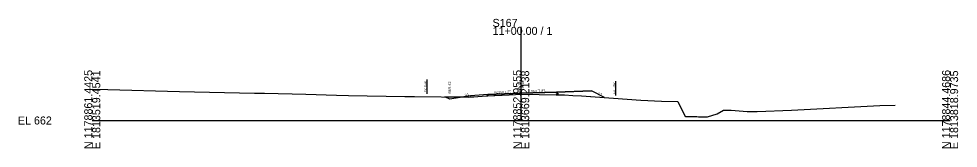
# Model space of a CAD drawing. Extents: x -26 to 6803, y -10 to 1023.
# Drawn here: x -25.7 to 302.8, y 490.3 to 535.6 of the extents above; entities that cross this region are included whole.
import ezdxf

# ---------------------------------------------------------------- set-up
doc = ezdxf.new("R2010")
doc.units = 0
for name, color, linetype in [('Default', 7, 'Continuous'), ('RD_EX_RW', 7, 'Continuous'), ('RD_GPK_XS_Cell', 7, 'Continuous'), ('RD_XS_Base', 7, 'Continuous'), ('RD_XS_EarthShd', 7, 'Continuous'), ('RD_XS_ExGround', 7, 'Continuous'), ('RD_XS_Misc_Line', 7, 'Continuous'), ('RD_XS_Pave', 7, 'Continuous'), ('RD_XS_TieSlope', 7, 'Continuous'), ('RD_XS_TX_Elev_EX', 7, 'Continuous'), ('RD_XS_TX_Elev_PR', 7, 'Continuous'), ('RD_XS_TX_Slope', 7, 'Continuous')]:
    doc.layers.add(name, color=color, linetype=linetype)

msp = doc.modelspace()

# ---------------------------------------------------------------- linework, layer by layer
at = {"layer": 'Default'}
for p, q in [((138.33, 509.14), (150, 509.54)), ((150, 509.54), (162.36, 509.94))]:
    msp.add_line(p, q, dxfattribs=at)
at = {"layer": 'RD_EX_RW'}
for p, q in [((117, 514.32), (117, 509.32)), ((183, 513.74), (183, 508.74))]:
    msp.add_line(p, q, dxfattribs=at)
at = {"layer": 'RD_GPK_XS_Cell'}
for p, q in [((150, 500), (150, 532.74)), ((0, 500), (150, 500)), ((150, 500), (300, 500))]:
    msp.add_line(p, q, dxfattribs=at)
at = {"layer": 'RD_XS_Base'}
for p, q in [((162.24, 508.94), (162.24, 509)), ((162.36, 508.94), (162.24, 508.94))]:
    msp.add_line(p, q, dxfattribs=at)
at = {"layer": 'RD_XS_EarthShd'}
for p, q in [((162.36, 509.94), (174.58, 510.34)), ((138.33, 509.14), (132.33, 508.64))]:
    msp.add_line(p, q, dxfattribs=at)
at = {"layer": 'RD_XS_ExGround'}
for p, q in [((0, 510.91), (5.4, 510.88)), ((5.4, 510.88), (30.5, 510.2)), ((30.5, 510.2), (56.74, 509.54)), ((56.74, 509.54), (60.18, 509.57)), ((60.18, 509.57), (74.68, 509.24)), ((74.68, 509.24), (85.43, 508.81)), ((85.43, 508.81), (89.62, 508.74)), ((89.62, 508.74), (109.26, 508.39)), ((109.26, 508.39), (111.56, 508.35)), ((111.56, 508.35), (112.73, 508.34)), ((112.73, 508.34), (131.5, 508.22)), ((131.5, 508.22), (132.22, 508.25)), ((132.22, 508.25), (133.4, 508.31)), ((133.4, 508.31), (137.76, 508.6)), ((137.76, 508.6), (145.82, 508.96)), ((145.82, 508.96), (150.23, 509.17)), ((150.23, 509.17), (162.3, 509)), ((162.3, 509), (163.67, 508.98)), ((163.67, 508.98), (165.12, 508.97)), ((165.12, 508.97), (168.12, 508.78)), ((168.12, 508.78), (171.06, 508.67)), ((171.06, 508.67), (191.82, 507.06)), ((191.82, 507.06), (199.12, 506.76)), ((199.12, 506.76), (204.8, 506.68)), ((204.8, 506.68), (207.29, 501.67)), ((218.51, 502.39), (220.74, 503.64)), ((220.74, 503.64), (223.41, 503.58)), ((223.41, 503.58), (228.98, 503.19)), ((228.98, 503.19), (232.48, 503.14)), ((232.48, 503.14), (244.57, 503.63)), ((244.57, 503.63), (275.48, 505.23)), ((275.48, 505.23), (280.76, 505.31)), ((207.29, 501.67), (207.6, 501.39)), ((207.6, 501.39), (210.92, 501.35)), ((210.92, 501.35), (211.4, 501.41)), ((211.4, 501.41), (212.02, 501.29)), ((212.02, 501.29), (215.11, 501.25)), ((215.11, 501.25), (218.51, 502.39))]:
    msp.add_line(p, q, dxfattribs=at)
at = {"layer": 'RD_XS_Misc_Line'}
for points in [[(162.24, 509), (162.3, 509), (162.86, 508.99), (162.86, 509.6), (162.36, 509.61), (162.36, 509.94), (150, 509.54), (138.33, 509.14), (138.33, 508.62), (145.82, 508.96), (150.23, 509.17)], [(162.24, 509), (162.3, 509), (162.86, 508.99), (162.86, 509.6), (162.36, 509.61), (162.36, 509.94), (150, 509.54), (138.33, 509.14), (138.33, 508.62), (145.82, 508.96), (150.23, 509.17)], [(162.24, 509), (162.3, 509), (162.86, 508.99), (162.86, 509.6), (162.36, 509.61), (162.36, 509.94), (150, 509.54), (138.33, 509.14), (138.33, 508.62), (145.82, 508.96), (150.23, 509.17)], [(162.36, 509.61), (162.36, 509.94), (150, 509.54), (138.33, 509.14), (138.33, 508.62), (145.82, 508.96), (150.23, 509.17), (162.24, 509), (162.3, 509), (162.86, 508.99), (162.86, 509.6)], [(162.36, 509.61), (162.36, 509.94), (150, 509.54), (138.33, 509.14), (138.33, 508.62), (145.82, 508.96), (150.23, 509.17), (162.24, 509), (162.3, 509), (162.86, 508.99), (162.86, 509.6)], [(162.86, 508.99), (163.67, 508.98), (165.12, 508.97), (168.12, 508.78), (171.06, 508.67), (179.18, 508.04), (174.58, 510.34), (162.36, 509.94), (162.36, 509.61), (162.86, 509.6)], [(162.86, 508.99), (163.67, 508.98), (165.12, 508.97), (168.12, 508.78), (171.06, 508.67), (179.18, 508.04), (174.58, 510.34), (162.36, 509.94), (162.36, 509.61), (162.86, 509.6)], [(162.86, 508.99), (163.67, 508.98), (165.12, 508.97), (168.12, 508.78), (171.06, 508.67), (179.18, 508.04), (174.58, 510.34), (162.36, 509.94), (162.36, 509.61), (162.86, 509.6)], [(179.18, 508.04), (174.58, 510.34), (162.36, 509.94), (162.36, 509.61), (162.86, 509.6), (162.86, 508.99), (163.67, 508.98), (165.12, 508.97), (168.12, 508.78), (171.06, 508.67)], [(179.18, 508.04), (174.58, 510.34), (162.36, 509.94), (162.36, 509.61), (162.86, 509.6), (162.86, 508.99), (163.67, 508.98), (165.12, 508.97), (168.12, 508.78), (171.06, 508.67)], [(129.89, 508.23), (125, 507.42), (123.29, 508.28)], [(129.89, 508.23), (131.5, 508.22), (132.22, 508.25), (133.4, 508.31), (137.76, 508.6), (138.33, 508.62), (138.33, 509.14), (132.33, 508.64)], [(129.89, 508.23), (131.5, 508.22), (132.22, 508.25), (133.4, 508.31), (137.76, 508.6), (138.33, 508.62), (138.33, 509.14), (132.33, 508.64)], [(129.89, 508.23), (131.5, 508.22), (132.22, 508.25), (133.4, 508.31), (137.76, 508.6), (138.33, 508.62), (138.33, 509.14), (132.33, 508.64)], [(132.33, 508.64), (129.89, 508.23), (131.5, 508.22), (132.22, 508.25), (133.4, 508.31), (137.76, 508.6), (138.33, 508.62), (138.33, 509.14)], [(132.33, 508.64), (129.89, 508.23), (131.5, 508.22), (132.22, 508.25), (133.4, 508.31), (137.76, 508.6), (138.33, 508.62), (138.33, 509.14)], [(162.24, 509), (162.3, 509), (162.86, 508.99), (162.86, 508.93), (162.36, 508.94), (162.24, 508.94)], [(162.24, 509), (162.3, 509), (162.86, 508.99), (162.86, 508.93), (162.36, 508.94), (162.24, 508.94)], [(162.24, 509), (162.3, 509), (162.86, 508.99), (162.86, 508.93), (162.36, 508.94), (162.24, 508.94)], [(162.86, 508.93), (162.86, 508.99), (162.3, 509), (162.24, 509), (162.24, 508.94), (162.36, 508.94)], [(162.86, 508.93), (162.86, 508.99), (162.3, 509), (162.24, 509), (162.24, 508.94), (162.36, 508.94)]]:
    msp.add_lwpolyline(points, close=True, dxfattribs=at)
at = {"layer": 'RD_XS_Pave'}
for p, q in [((162.36, 509.61), (162.36, 509.94)), ((162.86, 509.6), (162.36, 509.61)), ((162.86, 508.93), (162.86, 509.6)), ((138.33, 509.14), (138.33, 508.62)), ((162.36, 508.94), (162.86, 508.93))]:
    msp.add_line(p, q, dxfattribs=at)
at = {"layer": 'RD_XS_TieSlope'}
for p, q in [((179.18, 508.04), (174.58, 510.34)), ((125, 507.42), (123.29, 508.28)), ((132.33, 508.64), (125, 507.42))]:
    msp.add_line(p, q, dxfattribs=at)

# ---------------------------------------------------------------- texts
at = {"layer": 'RD_EX_RW'}
for p in [(116.94, 509.84), (182.94, 509.27)]:
    msp.add_text('EX. R/W', height=0.75, rotation=90, dxfattribs=at).set_placement(p)
at = {"layer": 'RD_GPK_XS_Cell'}
for s, p in [('S167', (140, 532.74)), ('11+00.00 / 1', (140, 529.94)), ('EL 662', (-26, 498.6))]:
    msp.add_text(s, height=2.8, dxfattribs=at).set_placement(p)
for s, p in [('N 1178861.4425', (0, 490)), ('E 1813519.4541', (2.8, 490)), ('N 1178852.9555', (150, 490)), ('E 1813669.2138', (152.8, 490)), ('N 1178844.4686', (300, 490)), ('E 1813818.9735', (302.8, 490))]:
    msp.add_text(s, height=2.8, rotation=90, dxfattribs=at).set_placement(p)
at = {"layer": 'RD_XS_TX_Elev_EX'}
msp.add_text('671.17', height=0.8, rotation=90, dxfattribs=at).set_placement((149.86, 510))
at = {"layer": 'RD_XS_TX_Elev_PR'}
for s, height, p in [('669.42', 1, (125.5, 509.42)), ('671.54', 0.8, (150.88, 510.53))]:
    msp.add_text(s, height=height, rotation=90, dxfattribs=at).set_placement(p)
at = {"layer": 'RD_XS_TX_Slope'}
for s, rotation, p in [('6:1', 14.0362, (130.35, 508.54)), ('0.034 FT./FT.', 1.9705, (140.56, 509.47)), ('0.032 FT./FT.', 1.857, (152.5, 509.87)), ('2:1', 333.4349, (176.79, 509.32))]:
    msp.add_text(s, height=0.75, rotation=rotation, dxfattribs=at).set_placement(p)

doc.saveas('drawing.dxf')
